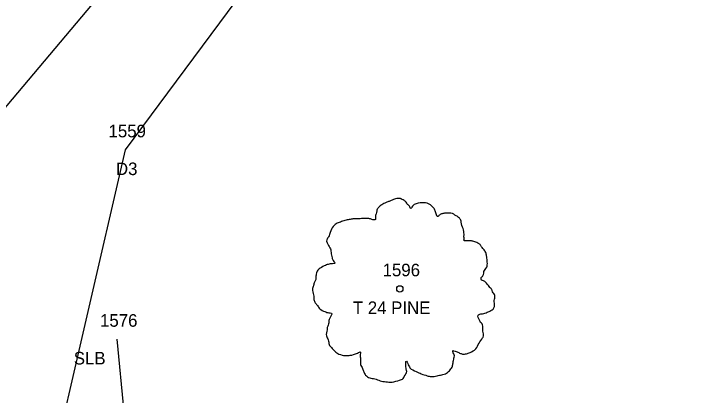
# Model space of a CAD drawing. Extents: x 1964982 to 1970452, y 1116335 to 1119906.
# Drawn here: x 1966585.2 to 1966640.3, y 1117463.6 to 1117493.9 of the extents above; entities that cross this region are included whole.
import ezdxf

# ---------------------------------------------------------------- set-up
doc = ezdxf.new("R2010")
doc.units = 0
for name, color, linetype in [('RD_EX_Driveway', 7, 'Continuous'), ('RD_EX_Driveway_txCode', 7, 'Continuous'), ('RD_EX_VEG', 7, 'Continuous'), ('RD_EX_VEG_txCode', 7, 'Continuous'), ('RD_SMD_Locator', 7, 'Continuous')]:
    doc.layers.add(name, color=color, linetype=linetype)

msp = doc.modelspace()

# ---------------------------------------------------------------- linework, layer by layer
at = {"layer": 'RD_EX_Driveway'}
for points in [[(1966578.028, 1117435.239), (1966571.581, 1117480.753), (1966567.97, 1117515.311), (1966576.556, 1117516.6), (1966582.112, 1117483.547), (1966603.624, 1117509.102), (1966634.749, 1117528.345), (1966662.085, 1117526.43), (1966689.524, 1117514.663), (1966711.523, 1117497.722), (1966730.008, 1117478.512), (1966744.031, 1117462.693), (1966734.107, 1117458.19)], [(1966589.3, 1117436.331), (1966587.977, 1117456.65), (1966594.083, 1117483.042), (1966609.697, 1117504.074), (1966638.325, 1117518.314), (1966661.317, 1117517.134), (1966685.434, 1117507.038), (1966705.558, 1117491.043), (1966722.871, 1117472.119), (1966734.107, 1117458.19)]]:
    msp.add_lwpolyline(points, dxfattribs=at)
at = {"layer": 'RD_EX_VEG'}
msp.add_line((1966597.045, 1117429.245), (1966593.432, 1117467.989), dxfattribs=at)
for centre, radius in [((1966615.898, 1117471.997), 0.25), ((1966615.898, 1117471.997), 0.25), ((1966615.886, 1117471.978), 0.0001), ((1966615.886, 1117471.978), 0.0001)]:
    msp.add_circle(centre, radius, dxfattribs=at)
for points in [[(1966616.03, 1117479.164), (1966615.73, 1117479.189), (1966615.405, 1117479.089), (1966615.156, 1117478.989), (1966614.931, 1117478.914), (1966614.706, 1117478.814), (1966614.406, 1117478.639), (1966614.181, 1117478.439), (1966614.056, 1117478.189), (1966614.006, 1117477.965), (1966613.956, 1117477.69), (1966613.956, 1117477.515), (1966613.831, 1117477.49), (1966613.681, 1117477.515), (1966613.431, 1117477.59), (1966613.181, 1117477.59), (1966612.931, 1117477.59), (1966612.582, 1117477.565), (1966612.232, 1117477.565), (1966611.957, 1117477.515), (1966611.632, 1117477.465), (1966611.257, 1117477.34), (1966610.907, 1117477.215), (1966610.608, 1117476.965), (1966610.358, 1117476.49), (1966610.233, 1117476.14), (1966610.083, 1117475.89), (1966610.233, 1117475.441), (1966610.408, 1117475.091), (1966610.433, 1117474.891), (1966610.508, 1117474.466), (1966610.608, 1117474.241), (1966610.732, 1117474.041), (1966610.658, 1117474.016), (1966610.283, 1117473.966), (1966609.983, 1117473.866), (1966609.558, 1117473.641), (1966609.333, 1117473.417), (1966609.233, 1117473.092), (1966609.208, 1117472.742), (1966609.108, 1117472.542), (1966609.033, 1117472.267), (1966609.008, 1117472.192), (1966608.958, 1117471.867), (1966609.058, 1117471.417), (1966609.083, 1117471.068), (1966609.208, 1117470.843), (1966609.358, 1117470.668), (1966609.533, 1117470.418), (1966609.933, 1117470.193), (1966610.258, 1117470.093), (1966610.458, 1117470.068), (1966610.283, 1117469.568), (1966610.233, 1117469.218), (1966610.108, 1117468.819), (1966610.108, 1117468.744), (1966610.058, 1117468.269), (1966610.208, 1117467.944), (1966610.283, 1117467.569), (1966610.458, 1117467.344), (1966610.732, 1117467.044), (1966611.057, 1117466.819), (1966611.557, 1117466.694), (1966611.957, 1117466.719), (1966612.532, 1117466.894), (1966612.782, 1117466.969), (1966612.757, 1117466.794), (1966612.782, 1117466.42), (1966612.782, 1117465.995), (1966612.931, 1117465.67), (1966613.031, 1117465.395), (1966613.181, 1117465.145), (1966613.506, 1117464.92), (1966613.906, 1117464.845), (1966614.331, 1117464.695), (1966614.781, 1117464.62), (1966615.28, 1117464.595), (1966615.88, 1117464.745), (1966616.155, 1117464.87), (1966616.255, 1117465.045), (1966616.455, 1117465.42), (1966616.405, 1117465.645), (1966616.43, 1117466.245), (1966616.53, 1117466.07), (1966616.705, 1117465.72), (1966617.205, 1117465.42), (1966617.604, 1117465.245), (1966618.079, 1117465.095), (1966618.379, 1117465.02), (1966618.854, 1117465.095), (1966619.229, 1117465.17), (1966619.604, 1117465.295), (1966619.903, 1117465.57), (1966620.078, 1117465.845), (1966620.128, 1117466.12), (1966620.203, 1117466.495), (1966620.253, 1117466.669)], [(1966616.03, 1117479.164), (1966615.73, 1117479.189), (1966615.405, 1117479.089), (1966615.156, 1117478.989), (1966614.931, 1117478.914), (1966614.706, 1117478.814), (1966614.406, 1117478.639), (1966614.181, 1117478.439), (1966614.056, 1117478.189), (1966614.006, 1117477.965), (1966613.956, 1117477.69), (1966613.956, 1117477.515), (1966613.831, 1117477.49), (1966613.681, 1117477.515), (1966613.431, 1117477.59), (1966613.181, 1117477.59), (1966612.931, 1117477.59), (1966612.582, 1117477.565), (1966612.232, 1117477.565), (1966611.957, 1117477.515), (1966611.632, 1117477.465), (1966611.257, 1117477.34), (1966610.907, 1117477.215), (1966610.608, 1117476.965), (1966610.358, 1117476.49), (1966610.233, 1117476.14), (1966610.083, 1117475.89), (1966610.233, 1117475.441), (1966610.408, 1117475.091), (1966610.433, 1117474.891), (1966610.508, 1117474.466), (1966610.608, 1117474.241), (1966610.732, 1117474.041), (1966610.658, 1117474.016), (1966610.283, 1117473.966), (1966609.983, 1117473.866), (1966609.558, 1117473.641), (1966609.333, 1117473.417), (1966609.233, 1117473.092), (1966609.208, 1117472.742), (1966609.108, 1117472.542), (1966609.033, 1117472.267), (1966609.008, 1117472.192), (1966608.958, 1117471.867), (1966609.058, 1117471.417), (1966609.083, 1117471.068), (1966609.208, 1117470.843), (1966609.358, 1117470.668), (1966609.533, 1117470.418), (1966609.933, 1117470.193), (1966610.258, 1117470.093), (1966610.458, 1117470.068), (1966610.283, 1117469.568), (1966610.233, 1117469.218), (1966610.108, 1117468.819), (1966610.108, 1117468.744), (1966610.058, 1117468.269), (1966610.208, 1117467.944), (1966610.283, 1117467.569), (1966610.458, 1117467.344), (1966610.732, 1117467.044), (1966611.057, 1117466.819), (1966611.557, 1117466.694), (1966611.957, 1117466.719), (1966612.532, 1117466.894), (1966612.782, 1117466.969), (1966612.757, 1117466.794), (1966612.782, 1117466.42), (1966612.782, 1117465.995), (1966612.931, 1117465.67), (1966613.031, 1117465.395), (1966613.181, 1117465.145), (1966613.506, 1117464.92), (1966613.906, 1117464.845), (1966614.331, 1117464.695), (1966614.781, 1117464.62), (1966615.28, 1117464.595), (1966615.88, 1117464.745), (1966616.155, 1117464.87), (1966616.255, 1117465.045), (1966616.455, 1117465.42), (1966616.405, 1117465.645), (1966616.43, 1117466.245), (1966616.53, 1117466.07), (1966616.705, 1117465.72), (1966617.205, 1117465.42), (1966617.604, 1117465.245), (1966618.079, 1117465.095), (1966618.379, 1117465.02), (1966618.854, 1117465.095), (1966619.229, 1117465.17), (1966619.604, 1117465.295), (1966619.903, 1117465.57), (1966620.078, 1117465.845), (1966620.128, 1117466.12), (1966620.203, 1117466.495), (1966620.253, 1117466.669)], [(1966620.253, 1117466.669), (1966620.178, 1117466.844), (1966620.128, 1117467.094), (1966620.203, 1117467.069), (1966620.378, 1117467.019), (1966620.653, 1117466.894), (1966620.878, 1117466.819), (1966621.203, 1117466.844), (1966621.478, 1117466.944), (1966621.928, 1117467.219), (1966622.202, 1117467.694), (1966622.477, 1117468.094), (1966622.552, 1117468.419), (1966622.502, 1117468.644), (1966622.477, 1117469.143), (1966622.277, 1117469.393), (1966622.227, 1117469.518), (1966622.127, 1117469.918), (1966622.202, 1117469.968), (1966622.477, 1117470.018), (1966622.852, 1117470.143), (1966623.127, 1117470.268), (1966623.352, 1117470.443), (1966623.427, 1117470.668), (1966623.402, 1117471.068), (1966623.452, 1117471.467), (1966623.377, 1117471.617), (1966623.277, 1117471.767), (1966623.202, 1117471.967), (1966623.052, 1117472.117), (1966622.952, 1117472.267), (1966622.852, 1117472.367), (1966622.727, 1117472.517), (1966622.552, 1117472.642), (1966622.402, 1117472.692), (1966622.352, 1117472.842), (1966622.502, 1117473.042), (1966622.552, 1117473.142), (1966622.577, 1117473.367), (1966622.802, 1117473.716), (1966622.852, 1117474.116), (1966622.802, 1117474.541), (1966622.752, 1117474.816), (1966622.602, 1117475.091), (1966622.402, 1117475.341), (1966622.277, 1117475.516), (1966622.102, 1117475.641), (1966621.778, 1117475.766), (1966621.528, 1117475.815), (1966621.178, 1117475.815), (1966620.978, 1117475.865), (1966621.003, 1117475.915), (1966621.003, 1117476.065), (1966621.003, 1117476.34), (1966620.928, 1117476.79), (1966620.778, 1117477.29), (1966620.778, 1117477.315), (1966620.678, 1117477.565), (1966620.453, 1117477.765), (1966620.278, 1117477.865), (1966620.078, 1117477.99), (1966619.828, 1117478.015), (1966619.529, 1117478.015), (1966619.254, 1117477.965), (1966619.054, 1117477.865), (1966618.879, 1117477.74), (1966618.804, 1117477.89), (1966618.704, 1117478.189), (1966618.654, 1117478.339), (1966618.504, 1117478.514), (1966618.279, 1117478.714), (1966617.829, 1117478.839), (1966617.205, 1117478.764), (1966616.905, 1117478.564), (1966616.755, 1117478.389), (1966616.705, 1117478.514), (1966616.505, 1117478.714), (1966616.405, 1117478.889), (1966616.23, 1117479.014), (1966616.08, 1117479.114), (1966615.98, 1117479.164)], [(1966620.253, 1117466.669), (1966620.178, 1117466.844), (1966620.128, 1117467.094), (1966620.203, 1117467.069), (1966620.378, 1117467.019), (1966620.653, 1117466.894), (1966620.878, 1117466.819), (1966621.203, 1117466.844), (1966621.478, 1117466.944), (1966621.928, 1117467.219), (1966622.202, 1117467.694), (1966622.477, 1117468.094), (1966622.552, 1117468.419), (1966622.502, 1117468.644), (1966622.477, 1117469.143), (1966622.277, 1117469.393), (1966622.227, 1117469.518), (1966622.127, 1117469.918), (1966622.202, 1117469.968), (1966622.477, 1117470.018), (1966622.852, 1117470.143), (1966623.127, 1117470.268), (1966623.352, 1117470.443), (1966623.427, 1117470.668), (1966623.402, 1117471.068), (1966623.452, 1117471.467), (1966623.377, 1117471.617), (1966623.277, 1117471.767), (1966623.202, 1117471.967), (1966623.052, 1117472.117), (1966622.952, 1117472.267), (1966622.852, 1117472.367), (1966622.727, 1117472.517), (1966622.552, 1117472.642), (1966622.402, 1117472.692), (1966622.352, 1117472.842), (1966622.502, 1117473.042), (1966622.552, 1117473.142), (1966622.577, 1117473.367), (1966622.802, 1117473.716), (1966622.852, 1117474.116), (1966622.802, 1117474.541), (1966622.752, 1117474.816), (1966622.602, 1117475.091), (1966622.402, 1117475.341), (1966622.277, 1117475.516), (1966622.102, 1117475.641), (1966621.778, 1117475.766), (1966621.528, 1117475.815), (1966621.178, 1117475.815), (1966620.978, 1117475.865), (1966621.003, 1117475.915), (1966621.003, 1117476.065), (1966621.003, 1117476.34), (1966620.928, 1117476.79), (1966620.778, 1117477.29), (1966620.778, 1117477.315), (1966620.678, 1117477.565), (1966620.453, 1117477.765), (1966620.278, 1117477.865), (1966620.078, 1117477.99), (1966619.828, 1117478.015), (1966619.529, 1117478.015), (1966619.254, 1117477.965), (1966619.054, 1117477.865), (1966618.879, 1117477.74), (1966618.804, 1117477.89), (1966618.704, 1117478.189), (1966618.654, 1117478.339), (1966618.504, 1117478.514), (1966618.279, 1117478.714), (1966617.829, 1117478.839), (1966617.205, 1117478.764), (1966616.905, 1117478.564), (1966616.755, 1117478.389), (1966616.705, 1117478.514), (1966616.505, 1117478.714), (1966616.405, 1117478.889), (1966616.23, 1117479.014), (1966616.08, 1117479.114), (1966615.98, 1117479.164)]]:
    msp.add_spline(points, degree=3, dxfattribs=at)
at = {"layer": 'RD_SMD_Locator'}
for centre in [(1966594.083, 1117483.042), (1966594.083, 1117483.042), (1966593.432, 1117467.989), (1966593.432, 1117467.989)]:
    msp.add_circle(centre, 0.001, dxfattribs=at)

# ---------------------------------------------------------------- texts
at = {"layer": 'RD_EX_Driveway_txCode'}
for s, p in [('1559', (1966592.736, 1117484.042)), ('1559', (1966592.736, 1117484.042)), ('D3', (1966593.327, 1117481.042)), ('D3', (1966593.327, 1117481.042))]:
    msp.add_text(s, height=1, dxfattribs=at).set_placement(p)
at = {"layer": 'RD_EX_VEG_txCode'}
for s, p in [('1596', (1966614.528, 1117472.997)), ('1596', (1966614.528, 1117472.997)), ('T 24 PINE', (1966612.162, 1117469.997)), ('T 24 PINE', (1966612.162, 1117469.997)), ('1576', (1966592.062, 1117468.989)), ('1576', (1966592.062, 1117468.989)), ('SLB', (1966589.975, 1117465.989)), ('SLB', (1966589.975, 1117465.989))]:
    msp.add_text(s, height=1, dxfattribs=at).set_placement(p)

doc.saveas('drawing.dxf')
